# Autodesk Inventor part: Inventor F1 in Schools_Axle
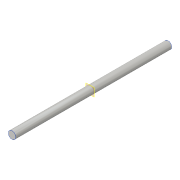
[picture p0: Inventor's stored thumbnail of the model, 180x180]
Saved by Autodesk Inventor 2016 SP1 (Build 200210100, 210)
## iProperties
Created: 2015-12
Part Number: Inventor F1 in Schools_Axle
Material: Aluminum 6061
Document SubType Name: Modeling
Designer: Autodesk Inc.
Density: 2.7 g/cm^3
Appearance: Aluminum - Flat
Author: Autodesk Inc
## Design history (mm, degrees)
feature "Body1"
workplane "Work Plane1"
body "Solid1"
